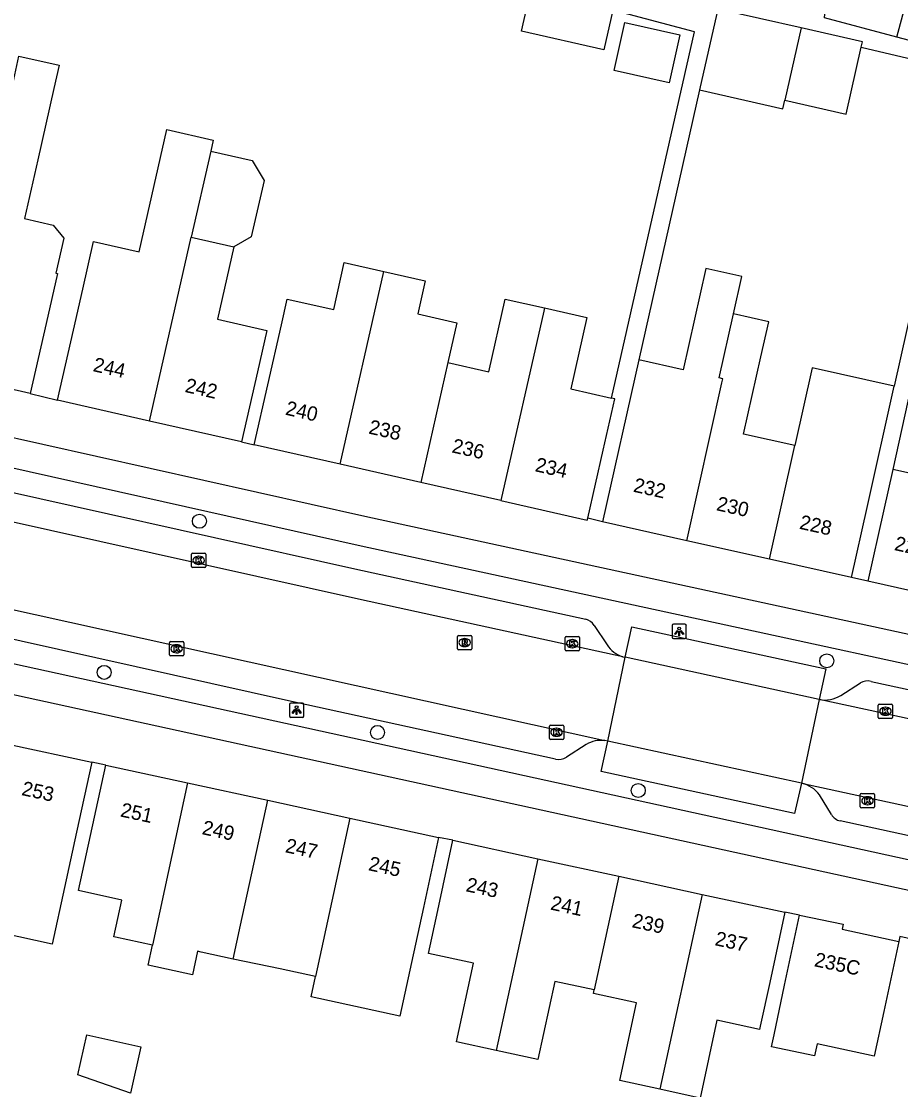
# Model space of a CAD drawing. Extents: x 158087 to 159494, y 382905 to 383981.
# Drawn here: x 158217.7 to 158278.9, y 383170.5 to 383245 of the extents above; entities that cross this region are included whole.
import ezdxf

# ---------------------------------------------------------------- set-up
doc = ezdxf.new("R2010")
doc.units = 0
for name, color, linetype in [('IMGEO_Boom', 7, 'Continuous'), ('IMGEO_Fietspad_gesloten', 7, 'Continuous'), ('IMGEO_Kolk', 7, 'Continuous'), ('IMGEO_Lichtpunt', 7, 'Continuous'), ('IMGEO_Pand', 7, 'Continuous'), ('IMGEO_Pand_nummerreeks', 7, 'Continuous'), ('IMGEO_Parkeervlak_open', 7, 'Continuous'), ('IMGEO_Rijbaan_lokaal_gesloten', 7, 'Continuous'), ('IMGEO_Rijbaan_lokaal_open', 7, 'Continuous'), ('IMGEO_Rioolput', 7, 'Continuous'), ('IMGEO_Voetpad_open', 7, 'Continuous')]:
    doc.layers.add(name, color=color, linetype=linetype)

msp = doc.modelspace()

# ---------------------------------------------------------------- linework, layer by layer
at = {"layer": 'IMGEO_Boom'}
for centre in [(158230.091, 383210.124), (158273.785, 383200.399), (158223.458, 383199.595), (158242.492, 383195.409), (158260.658, 383191.365)]:
    msp.add_circle(centre, 0.489, dxfattribs=at)
at = {"layer": 'IMGEO_Fietspad_gesloten'}
for points in [[(158184.729, 383222.86), (158195.608, 383220.653), (158207.946, 383218.002), (158241.603, 383210.483), (158310.224, 383195.595)], [(158321.216, 383191.287), (158309.726, 383193.572), (158241.35, 383208.396), (158202.859, 383217.005), (158187.053, 383220.294)], [(158306.699, 383178.457), (158187.059, 383204.599), (158174.364, 383207.03)], [(158201.292, 383203.669), (158307.14, 383180.487)]]:
    msp.add_lwpolyline(points, dxfattribs=at)
at = {"layer": 'IMGEO_Kolk'}
for p, q in [((158229.541, 383206.976), (158229.541, 383207.828)), ((158229.616, 383207.902), (158230.468, 383207.902)), ((158230.542, 383207.828), (158230.542, 383206.976)), ((158230.052, 383207.122), (158230.027, 383207.122)), ((158230.029, 383207.682), (158230.054, 383207.682)), ((158230.468, 383206.902), (158229.616, 383206.902)), ((158255.561, 383201.168), (158255.561, 383202.02)), ((158255.636, 383202.094), (158256.488, 383202.094)), ((158256.049, 383201.874), (158256.074, 383201.874)), ((158256.562, 383202.02), (158256.562, 383201.168)), ((158228.002, 383200.812), (158228.002, 383201.664)), ((158228.077, 383201.738), (158228.929, 383201.738)), ((158228.49, 383201.518), (158228.515, 383201.518)), ((158229.003, 383201.664), (158229.003, 383200.812)), ((158256.072, 383201.314), (158256.047, 383201.314)), ((158228.929, 383200.738), (158228.077, 383200.738)), ((158228.513, 383200.958), (158228.488, 383200.958)), ((158256.488, 383201.094), (158255.636, 383201.094)), ((158277.371, 383196.459), (158277.371, 383197.311)), ((158277.446, 383197.385), (158278.298, 383197.385)), ((158277.859, 383197.165), (158277.884, 383197.165)), ((158278.372, 383197.311), (158278.372, 383196.459)), ((158254.538, 383195.918), (158255.39, 383195.918)), ((158278.298, 383196.385), (158277.446, 383196.385)), ((158277.882, 383196.605), (158277.857, 383196.605)), ((158254.463, 383194.992), (158254.463, 383195.844)), ((158254.951, 383195.698), (158254.976, 383195.698)), ((158255.464, 383195.844), (158255.464, 383194.992)), ((158255.39, 383194.918), (158254.538, 383194.918)), ((158254.974, 383195.138), (158254.949, 383195.138)), ((158276.118, 383190.224), (158276.118, 383191.076)), ((158276.193, 383191.15), (158277.045, 383191.15)), ((158276.606, 383190.93), (158276.631, 383190.93)), ((158277.119, 383191.076), (158277.119, 383190.224)), ((158277.045, 383190.15), (158276.193, 383190.15)), ((158276.629, 383190.37), (158276.604, 383190.37))]:
    msp.add_line(p, q, dxfattribs=at)
for points in [[(158229.541, 383206.976), (158229.541, 383207.828)], [(158229.616, 383207.902), (158230.468, 383207.902)], [(158230.542, 383207.828), (158230.542, 383206.976)], [(158229.862, 383207.602), (158229.985, 383207.602), (158229.985, 383207.451), (158230.115, 383207.602), (158230.279, 383207.602), (158230.133, 383207.451), (158230.286, 383207.202), (158230.134, 383207.202), (158230.049, 383207.366), (158229.985, 383207.299), (158229.985, 383207.202), (158229.862, 383207.202), (158229.862, 383207.602)], [(158230.468, 383206.902), (158229.616, 383206.902)], [(158255.561, 383201.168), (158255.561, 383202.02)], [(158255.636, 383202.094), (158256.488, 383202.094)], [(158256.562, 383202.02), (158256.562, 383201.168)], [(158228.002, 383200.812), (158228.002, 383201.664)], [(158228.077, 383201.738), (158228.929, 383201.738)], [(158228.323, 383201.438), (158228.446, 383201.438), (158228.446, 383201.287), (158228.576, 383201.438), (158228.74, 383201.438), (158228.594, 383201.287), (158228.747, 383201.038), (158228.595, 383201.038), (158228.51, 383201.202), (158228.446, 383201.135), (158228.446, 383201.038), (158228.323, 383201.038), (158228.323, 383201.438)], [(158229.003, 383201.664), (158229.003, 383200.812)], [(158255.882, 383201.794), (158256.005, 383201.794), (158256.005, 383201.643), (158256.135, 383201.794), (158256.299, 383201.794), (158256.153, 383201.643), (158256.306, 383201.394), (158256.154, 383201.394), (158256.069, 383201.558), (158256.005, 383201.491), (158256.005, 383201.394), (158255.882, 383201.394), (158255.882, 383201.794)], [(158228.929, 383200.738), (158228.077, 383200.738)], [(158256.488, 383201.094), (158255.636, 383201.094)], [(158277.371, 383196.459), (158277.371, 383197.311)], [(158277.446, 383197.385), (158278.298, 383197.385)], [(158277.692, 383197.085), (158277.815, 383197.085), (158277.815, 383196.934), (158277.945, 383197.085), (158278.109, 383197.085), (158277.963, 383196.934), (158278.116, 383196.685), (158277.964, 383196.685), (158277.879, 383196.849), (158277.815, 383196.782), (158277.815, 383196.685), (158277.692, 383196.685), (158277.692, 383197.085)], [(158278.372, 383197.311), (158278.372, 383196.459)], [(158254.538, 383195.918), (158255.39, 383195.918)], [(158278.298, 383196.385), (158277.446, 383196.385)], [(158254.463, 383194.992), (158254.463, 383195.844)], [(158254.784, 383195.618), (158254.907, 383195.618), (158254.907, 383195.467), (158255.037, 383195.618), (158255.201, 383195.618), (158255.055, 383195.467), (158255.208, 383195.218), (158255.056, 383195.218), (158254.971, 383195.382), (158254.907, 383195.315), (158254.907, 383195.218), (158254.784, 383195.218), (158254.784, 383195.618)], [(158255.464, 383195.844), (158255.464, 383194.992)], [(158255.39, 383194.918), (158254.538, 383194.918)], [(158276.118, 383190.224), (158276.118, 383191.076)], [(158276.193, 383191.15), (158277.045, 383191.15)], [(158276.439, 383190.85), (158276.562, 383190.85), (158276.562, 383190.699), (158276.692, 383190.85), (158276.856, 383190.85), (158276.71, 383190.699), (158276.863, 383190.45), (158276.711, 383190.45), (158276.626, 383190.614), (158276.562, 383190.547), (158276.562, 383190.45), (158276.439, 383190.45), (158276.439, 383190.85)], [(158277.119, 383191.076), (158277.119, 383190.224)], [(158277.045, 383190.15), (158276.193, 383190.15)]]:
    msp.add_lwpolyline(points, dxfattribs=at)
for centre, start, end in [((158229.618, 383207.826), 91.55205, 178.44795), ((158229.618, 383207.826), 91.55205, 178.44795), ((158230.466, 383207.826), 1.55205, 88.44795), ((158230.466, 383207.826), 1.55205, 88.44795), ((158229.618, 383206.978), 181.55205, 268.44795), ((158229.618, 383206.978), 181.55205, 268.44795), ((158230.466, 383206.978), 271.55205, 358.44795), ((158230.466, 383206.978), 271.55205, 358.44795), ((158255.638, 383202.018), 91.55205, 178.44795), ((158255.638, 383202.018), 91.55205, 178.44795), ((158256.486, 383202.018), 1.55205, 88.44795), ((158256.486, 383202.018), 1.55205, 88.44795), ((158228.079, 383201.662), 91.55205, 178.44795), ((158228.079, 383201.662), 91.55205, 178.44795), ((158228.927, 383201.662), 1.55205, 88.44795), ((158228.927, 383201.662), 1.55205, 88.44795), ((158255.638, 383201.17), 181.55205, 268.44795), ((158255.638, 383201.17), 181.55205, 268.44795), ((158256.486, 383201.17), 271.55205, 358.44795), ((158256.486, 383201.17), 271.55205, 358.44795), ((158228.079, 383200.814), 181.55205, 268.44795), ((158228.079, 383200.814), 181.55205, 268.44795), ((158228.927, 383200.814), 271.55205, 358.44795), ((158228.927, 383200.814), 271.55205, 358.44795), ((158277.448, 383197.309), 91.55205, 178.44795), ((158277.448, 383197.309), 91.55205, 178.44795), ((158278.296, 383197.309), 1.55205, 88.44795), ((158278.296, 383197.309), 1.55205, 88.44795), ((158254.54, 383195.842), 91.55205, 178.44795), ((158254.54, 383195.842), 91.55205, 178.44795), ((158255.388, 383195.842), 1.55205, 88.44795), ((158255.388, 383195.842), 1.55205, 88.44795), ((158277.448, 383196.461), 181.55205, 268.44795), ((158277.448, 383196.461), 181.55205, 268.44795), ((158278.296, 383196.461), 271.55205, 358.44795), ((158278.296, 383196.461), 271.55205, 358.44795), ((158254.54, 383194.994), 181.55205, 268.44795), ((158254.54, 383194.994), 181.55205, 268.44795), ((158255.388, 383194.994), 271.55205, 358.44795), ((158255.388, 383194.994), 271.55205, 358.44795), ((158276.195, 383191.074), 91.55205, 178.44795), ((158276.195, 383191.074), 91.55205, 178.44795), ((158277.043, 383191.074), 1.55205, 88.44795), ((158277.043, 383191.074), 1.55205, 88.44795), ((158276.195, 383190.226), 181.55205, 268.44795), ((158276.195, 383190.226), 181.55205, 268.44795), ((158277.043, 383190.226), 271.55205, 358.44795), ((158277.043, 383190.226), 271.55205, 358.44795)]:
    msp.add_arc(centre, 0.0765, start, end, dxfattribs=at)
for centre, major_axis, ratio, start_param, end_param in [((158230.028, 383207.402), (-0.387, 0.002), 0.722429, 4.712389, 7.853982), ((158230.053, 383207.402), (-0.39, 0.002), 0.717154, 1.570796, 4.712389), ((158256.048, 383201.594), (-0.387, 0.002), 0.722429, 4.712389, 7.853982), ((158256.073, 383201.594), (-0.39, 0.002), 0.717154, 1.570796, 4.712389), ((158228.489, 383201.238), (-0.387, 0.002), 0.722429, 4.712389, 7.853982), ((158228.514, 383201.238), (-0.39, 0.002), 0.717154, 1.570796, 4.712389), ((158277.858, 383196.885), (-0.387, 0.002), 0.722429, 4.712389, 7.853982), ((158277.883, 383196.885), (-0.39, 0.002), 0.717154, 1.570796, 4.712389), ((158254.95, 383195.418), (-0.387, 0.002), 0.722429, 4.712389, 7.853982), ((158254.975, 383195.418), (-0.39, 0.002), 0.717154, 1.570796, 4.712389), ((158276.605, 383190.65), (-0.387, 0.002), 0.722429, 4.712389, 7.853982), ((158276.63, 383190.65), (-0.39, 0.002), 0.717154, 1.570796, 4.712389)]:
    msp.add_ellipse(centre, major_axis=major_axis, ratio=ratio, start_param=start_param, end_param=end_param, dxfattribs=at)
at = {"layer": 'IMGEO_Lichtpunt'}
for p, q in [((158263.008, 383202.854), (158263.008, 383202.047)), ((158263.008, 383202.854), (158263.008, 383202.047)), ((158263.91, 383202.949), (158263.102, 383202.949)), ((158263.91, 383202.949), (158263.102, 383202.949)), ((158264.004, 383202.047), (158264.004, 383202.854)), ((158264.004, 383202.047), (158264.004, 383202.854)), ((158263.102, 383201.953), (158263.91, 383201.953)), ((158263.102, 383201.953), (158263.91, 383201.953)), ((158237.265, 383197.458), (158236.457, 383197.458)), ((158237.265, 383197.458), (158236.457, 383197.458)), ((158236.363, 383197.363), (158236.363, 383196.556)), ((158236.363, 383197.363), (158236.363, 383196.556)), ((158237.359, 383196.556), (158237.359, 383197.363)), ((158237.359, 383196.556), (158237.359, 383197.363)), ((158236.457, 383196.462), (158237.265, 383196.462)), ((158236.457, 383196.462), (158237.265, 383196.462))]:
    msp.add_line(p, q, dxfattribs=at)
for points in [[(158263.382, 383202.518), (158263.421, 383202.49), (158263.233, 383202.228), (158263.195, 383202.255), (158263.382, 383202.518)], [(158263.484, 383202.47), (158263.531, 383202.47), (158263.531, 383202.148), (158263.484, 383202.148), (158263.484, 383202.47)], [(158263.594, 383202.49), (158263.632, 383202.517), (158263.819, 383202.255), (158263.78, 383202.227), (158263.594, 383202.49)], [(158236.737, 383197.027), (158236.776, 383196.999), (158236.588, 383196.737), (158236.55, 383196.764), (158236.737, 383197.027)], [(158236.839, 383196.979), (158236.886, 383196.979), (158236.886, 383196.657), (158236.839, 383196.657), (158236.839, 383196.979)], [(158236.949, 383196.999), (158236.987, 383197.026), (158237.174, 383196.764), (158237.135, 383196.736), (158236.949, 383196.999)]]:
    msp.add_lwpolyline(points, dxfattribs=at)
for centre in [(158263.507, 383202.652), (158236.862, 383197.161)]:
    msp.add_circle(centre, 0.0994, dxfattribs=at)
for centre, start, end in [((158263.102, 383202.854), 90, 180), ((158263.102, 383202.854), 90, 180), ((158263.91, 383202.854), 0, 90), ((158263.91, 383202.854), 0, 90), ((158263.102, 383202.047), 180, 270), ((158263.102, 383202.047), 180, 270), ((158263.91, 383202.047), 270, 0), ((158263.91, 383202.047), 270, 360), ((158236.457, 383197.363), 90, 180), ((158236.457, 383197.363), 90, 180), ((158237.265, 383197.363), 0, 90), ((158237.265, 383197.363), 0, 90), ((158236.457, 383196.556), 180, 270), ((158236.457, 383196.556), 180, 270), ((158237.265, 383196.556), 270, 0), ((158237.265, 383196.556), 270, 360)]:
    msp.add_arc(centre, 0.0946, start, end, dxfattribs=at)
at = {"layer": 'IMGEO_Pand'}
for points in [[(158278.661, 383243.862), (158273.633, 383245.192), (158273.888, 383248.033), (158273.927, 383248.468)], [(158258.896, 383245.738), (158258.267, 383242.97), (158252.526, 383244.275), (158253.155, 383247.044)], [(158278.661, 383243.862), (158279.491, 383246.996)], [(158272.004, 383244.494), (158266.192, 383245.815), (158266.121, 383245.505)], [(158266.121, 383245.505), (158264.911, 383240.184)], [(158259.727, 383244.88), (158263.56, 383244.009), (158262.799, 383240.665), (158258.967, 383241.536), (158259.727, 383244.88)], [(158272.004, 383244.494), (158270.865, 383239.454)], [(158276.191, 383243.15), (158276.276, 383243.522), (158272.004, 383244.494)], [(158283.429, 383242.6), (158278.661, 383243.862)], [(158270.865, 383239.454), (158275.131, 383238.484), (158276.191, 383243.15)], [(158217.121, 383240.756), (158217.156, 383240.912), (158217.524, 383242.534), (158220.325, 383241.898), (158219.958, 383240.276), (158218.834, 383235.313), (158217.905, 383231.213), (158219.901, 383230.761), (158220.655, 383229.852), (158220.101, 383227.402), (158220.198, 383227.38), (158219.413, 383223.914), (158218.308, 383219.037)], [(158264.911, 383240.184), (158270.731, 383238.86), (158270.865, 383239.454)], [(158220.214, 383218.552), (158221.318, 383223.429), (158221.969, 383226.304), (158222.72, 383229.62), (158225.89, 383228.902), (158227.818, 383237.415), (158231.053, 383236.682), (158230.878, 383235.909)], [(158230.878, 383235.909), (158229.524, 383229.927)], [(158230.878, 383235.909), (158233.762, 383235.256), (158234.594, 383233.877), (158233.704, 383229.948), (158232.497, 383229.254)], [(158226.62, 383217.101), (158229.524, 383229.927)], [(158229.524, 383229.927), (158232.497, 383229.254)], [(158232.497, 383229.254), (158231.352, 383224.199), (158234.785, 383223.421), (158234.13, 383220.527), (158233.025, 383215.65)], [(158233.913, 383215.451), (158235.806, 383223.808), (158236.214, 383225.61), (158239.444, 383224.879), (158240.184, 383228.145), (158242.938, 383227.522)], [(158239.898, 383214.095), (158242.938, 383227.522)], [(158242.938, 383227.522), (158245.813, 383226.871), (158245.293, 383224.574), (158248.03, 383223.954), (158247.402, 383221.182)], [(158267.293, 383224.576), (158267.873, 383227.174), (158265.351, 383227.737), (158263.775, 383220.678), (158260.691, 383221.367)], [(158247.402, 383221.182), (158250.24, 383220.539), (158251.388, 383225.608), (158254.126, 383224.988)], [(158254.126, 383224.988), (158254.08, 383224.774), (158251.088, 383211.561)], [(158254.126, 383224.988), (158257.079, 383224.319), (158255.953, 383219.347), (158258.79, 383218.705)], [(158264.034, 383208.766), (158266.483, 383219.773), (158266.547, 383220.059), (158266.296, 383220.115), (158267.293, 383224.576)], [(158271.563, 383215.394), (158267.997, 383216.19), (158269.199, 383221.573), (158269.747, 383224.028), (158267.293, 383224.576)], [(158260.691, 383221.367), (158258.169, 383210.075)], [(158247.402, 383221.182), (158245.51, 383212.824)], [(158278.489, 383219.543), (158272.77, 383220.82), (158271.563, 383215.394)], [(158218.308, 383219.037), (158212.513, 383220.349)], [(158275.511, 383206.204), (158276.601, 383211.084), (158278.489, 383219.543)], [(158226.62, 383217.101), (158220.214, 383218.552)], [(158257.133, 383210.332), (158258.208, 383215.075), (158259.019, 383218.653), (158258.79, 383218.705)], [(158284.791, 383217.904), (158282.206, 383218.481), (158281.013, 383213.138), (158278.387, 383213.724)], [(158233.025, 383215.65), (158226.62, 383217.101)], [(158239.898, 383214.095), (158233.913, 383215.451)], [(158269.802, 383207.478), (158271.563, 383215.394)], [(158245.51, 383212.824), (158239.898, 383214.095)], [(158278.387, 383213.724), (158277.74, 383210.824), (158276.65, 383205.944)], [(158251.088, 383211.561), (158245.51, 383212.824)], [(158251.088, 383211.561), (158257.103, 383210.198), (158257.133, 383210.332)], [(158264.034, 383208.766), (158258.169, 383210.075)], [(158269.802, 383207.478), (158264.034, 383208.766)], [(158275.511, 383206.204), (158269.802, 383207.478)], [(158281.908, 383204.77), (158276.65, 383205.944)], [(158216.769, 383194.601), (158222.593, 383193.338)], [(158222.593, 383193.338), (158221.534, 383188.452), (158220.7, 383184.605), (158219.846, 383180.666), (158214.014, 383181.93), (158214.361, 383183.524)], [(158226.819, 383180.593), (158224.248, 383181.15), (158224.124, 383181.177), (158224.678, 383183.73), (158221.677, 383184.393), (158222.511, 383188.239), (158223.57, 383193.125)], [(158223.57, 383193.125), (158229.271, 383191.889)], [(158229.271, 383191.889), (158226.819, 383180.593)], [(158229.271, 383191.889), (158234.849, 383190.68)], [(158232.449, 383179.618), (158232.96, 383181.975), (158234.849, 383190.68)], [(158234.849, 383190.68), (158240.563, 383189.441)], [(158240.563, 383189.441), (158238.168, 383178.396)], [(158240.563, 383189.441), (158246.75, 383188.1)], [(158246.75, 383188.1), (158245.69, 383183.214), (158244.859, 383179.381), (158244.049, 383175.647), (158237.863, 383176.988), (158238.168, 383178.396)], [(158250.764, 383173.258), (158247.985, 383173.861), (158249.172, 383179.339), (158246.042, 383180.017), (158246.69, 383183.006), (158247.75, 383187.892)], [(158247.75, 383187.892), (158253.659, 383186.611)], [(158253.659, 383186.611), (158250.764, 383173.258)], [(158253.659, 383186.611), (158259.301, 383185.387)], [(158259.301, 383185.387), (158257.584, 383177.468)], [(158259.301, 383185.387), (158265.108, 383184.129)], [(158265.108, 383184.129), (158262.164, 383170.543)], [(158265.108, 383184.129), (158270.874, 383182.878)], [(158270.874, 383182.878), (158269.814, 383177.992), (158269.155, 383174.953), (158269.106, 383174.717), (158266.14, 383175.36), (158264.964, 383169.936), (158262.164, 383170.543)], [(158278.795, 383180.853), (158277.753, 383175.963), (158277.096, 383172.86), (158273.107, 383173.706), (158272.932, 383172.878), (158269.936, 383173.514), (158270.112, 383174.341), (158270.849, 383177.797), (158271.892, 383182.686)], [(158271.892, 383182.686), (158274.926, 383182.039), (158274.853, 383181.694), (158278.795, 383180.853)], [(158232.449, 383179.618), (158230.211, 383180.104), (158229.961, 383180.158), (158229.608, 383178.531), (158226.517, 383179.201), (158226.819, 383180.593)], [(158238.168, 383178.396), (158235.706, 383178.93), (158232.449, 383179.618)], [(158257.584, 383177.468), (158254.839, 383178.063), (158253.661, 383172.63), (158250.764, 383173.258)], [(158262.164, 383170.543), (158259.364, 383171.149), (158260.54, 383176.575), (158257.533, 383177.226), (158257.584, 383177.468)], [(158225.298, 383170.285), (158221.633, 383171.548), (158222.249, 383174.343), (158226.01, 383173.513), (158225.298, 383170.285)]]:
    msp.add_lwpolyline(points, dxfattribs=at)
at = {"layer": 'IMGEO_Parkeervlak_open'}
for points in [[(158186.095, 383218.765), (158192.996, 383217.388), (158201.806, 383215.545), (158240.906, 383206.806), (158256.997, 383203.295)], [(158254.9, 383193.55), (158236.292, 383197.608), (158201.626, 383205.353)], [(158257.594, 383202.867), (158258.48, 383201.517)], [(158259.738, 383200.649), (158260.208, 383202.76), (158273.709, 383199.843), (158273.257, 383197.701)], [(158276.869, 383198.965), (158310.165, 383191.768), (158320.914, 383189.662)], [(158274.761, 383197.987), (158276.124, 383198.855)], [(158257.032, 383194.571), (158255.648, 383193.69)], [(158272.028, 383191.873), (158271.532, 383189.764), (158258.073, 383192.693), (158258.527, 383194.795)], [(158274.112, 383189.687), (158273.277, 383191.058)], [(158317.844, 383179.993), (158304.134, 383182.846), (158274.722, 383189.241)]]:
    msp.add_lwpolyline(points, dxfattribs=at)
for centre, radius, start, end in [((158256.715, 383202.271), 1.062, 34.13748, 74.58769), ((158260.159, 383202.595), 1.995, 212.68951, 252.85147), ((158276.62, 383198.071), 0.928, 74.45828, 122.33991), ((158273.641, 383199.778), 2.113, 259.52241, 302.01117), ((158258.076, 383192.819), 2.039, 82.92928, 120.79451), ((158255.109, 383194.503), 0.975, 257.63992, 303.56239), ((158271.571, 383189.807), 2.116, 36.23738, 77.51196), ((158274.955, 383190.2), 0.987, 211.31108, 256.34429)]:
    msp.add_arc(centre, radius, start, end, dxfattribs=at)
at = {"layer": 'IMGEO_Rijbaan_lokaal_gesloten'}
for points in [[(158259.571, 383200.688), (158241.385, 383204.641), (158201.478, 383213.544), (158175.54, 383218.731)], [(158174.939, 383212.762), (158206.139, 383206.386), (158258.327, 383194.843)], [(158259.571, 383200.688), (158259.738, 383200.649)], [(158309.28, 383189.934), (158273.257, 383197.701)], [(158258.527, 383194.795), (158258.327, 383194.843)], [(158272.028, 383191.873), (158304.012, 383184.929)]]:
    msp.add_lwpolyline(points, dxfattribs=at)
at = {"layer": 'IMGEO_Rijbaan_lokaal_open'}
for points in [[(158258.527, 383194.795), (158259.738, 383200.649)], [(158273.257, 383197.701), (158259.738, 383200.649)], [(158273.257, 383197.701), (158272.028, 383191.873)], [(158272.028, 383191.873), (158258.527, 383194.795)]]:
    msp.add_lwpolyline(points, dxfattribs=at)
at = {"layer": 'IMGEO_Rioolput'}
for p, q in [((158248.064, 383201.242), (158248.064, 383202.094)), ((158248.139, 383202.168), (158248.991, 383202.168)), ((158248.552, 383201.948), (158248.577, 383201.948)), ((158249.065, 383202.094), (158249.065, 383201.242)), ((158248.991, 383201.168), (158248.139, 383201.168)), ((158248.575, 383201.388), (158248.55, 383201.388))]:
    msp.add_line(p, q, dxfattribs=at)
for points in [[(158248.064, 383201.242), (158248.064, 383202.094)], [(158248.139, 383202.168), (158248.991, 383202.168)], [(158248.653, 383201.866), (158248.401, 383201.868), (158248.401, 383201.468)], [(158249.065, 383202.094), (158249.065, 383201.242)], [(158248.991, 383201.168), (158248.139, 383201.168)], [(158248.401, 383201.468), (158248.525, 383201.468), (158248.525, 383201.63), (158248.536, 383201.63)], [(158248.579, 383201.787), (158248.525, 383201.787), (158248.525, 383201.706)], [(158248.525, 383201.706), (158248.577, 383201.706)], [(158248.583, 383201.601), (158248.654, 383201.468), (158248.794, 383201.468), (158248.729, 383201.594)]]:
    msp.add_lwpolyline(points, dxfattribs=at)
for centre, radius, start, end in [((158248.141, 383202.092), 0.0765, 91.55205, 178.44795), ((158248.141, 383202.092), 0.0765, 91.55205, 178.44795), ((158248.652, 383201.756), 0.109, 350.36119, 89.41601), ((158248.989, 383202.092), 0.0765, 1.55205, 88.44795), ((158248.989, 383202.092), 0.0765, 1.55205, 88.44795), ((158248.141, 383201.244), 0.0765, 181.55205, 268.44795), ((158248.141, 383201.244), 0.0765, 181.55205, 268.44795), ((158248.535, 383201.577), 0.0533, 26.02933, 88.69889), ((158248.561, 383201.895), 0.19, 274.7715, 282.96867), ((158248.585, 383201.691), 0.0964, 77.00612, 93.18647), ((158248.599, 383201.748), 0.0378, 276.66336, 79.67722), ((158248.65, 383201.756), 0.112, 277.58423, 350.98172), ((158248.634, 383201.541), 0.108, 29.51342, 73.79051), ((158248.989, 383201.244), 0.0765, 271.55205, 358.44795), ((158248.989, 383201.244), 0.0765, 271.55205, 358.44795)]:
    msp.add_arc(centre, radius, start, end, dxfattribs=at)
for centre, major_axis, ratio, start_param, end_param in [((158248.551, 383201.668), (-0.387, 0.002), 0.722429, 4.712389, 7.853982), ((158248.576, 383201.668), (-0.39, 0.002), 0.717154, 1.570796, 4.712389)]:
    msp.add_ellipse(centre, major_axis=major_axis, ratio=ratio, start_param=start_param, end_param=end_param, dxfattribs=at)
at = {"layer": 'IMGEO_Voetpad_open'}
for points in [[(158258.79, 383218.705), (158264.566, 383244.222), (158258.896, 383245.738)], [(158276.191, 383243.15), (158283.383, 383241.47), (158278.489, 383219.543)], [(158264.911, 383240.184), (158260.691, 383221.367)], [(158282.666, 383233.182), (158278.387, 383213.724)], [(158218.308, 383219.037), (158220.214, 383218.552)], [(158233.025, 383215.65), (158233.913, 383215.451)], [(158258.169, 383210.075), (158257.133, 383210.332)], [(158276.65, 383205.944), (158275.511, 383206.204)], [(158223.57, 383193.125), (158222.593, 383193.338)], [(158247.75, 383187.892), (158246.75, 383188.1)], [(158271.892, 383182.686), (158270.874, 383182.878)], [(158281.898, 383180.525), (158278.879, 383181.201), (158278.795, 383180.853)]]:
    msp.add_lwpolyline(points, dxfattribs=at)

# ---------------------------------------------------------------- texts
at = {"layer": 'IMGEO_Pand_nummerreeks'}
for s, rotation, p in [('244', 347.2345, (158222.629, 383220.589)), ('242', 347.23653, (158229.032, 383219.139)), ('240', 347.24023, (158236.028, 383217.556)), ('238', 347.24023, (158241.826, 383216.243)), ('236', 347.23227, (158247.621, 383214.931)), ('234', 347.2345, (158253.418, 383213.617)), ('232', 347.41785, (158260.261, 383212.19)), ('230', 347.41785, (158266.048, 383210.899)), ('228', 347.41785, (158271.828, 383209.609)), ('226', 347.41785, (158278.443, 383208.125)), ('253', 347.76893, (158217.656, 383191.052)), ('251', 347.76735, (158224.535, 383189.56)), ('249', 347.76735, (158230.22, 383188.327)), ('247', 347.76735, (158236.015, 383187.071)), ('245', 347.76735, (158241.81, 383185.815)), ('243', 347.76588, (158248.598, 383184.352)), ('241', 347.76588, (158254.489, 383183.075)), ('239', 347.76588, (158260.16, 383181.845)), ('237', 347.76588, (158265.941, 383180.592)), ('235C', 348.00226, (158272.862, 383179.126))]:
    msp.add_text(s, height=1, rotation=rotation, dxfattribs=at).set_placement(p)

doc.saveas('drawing.dxf')
